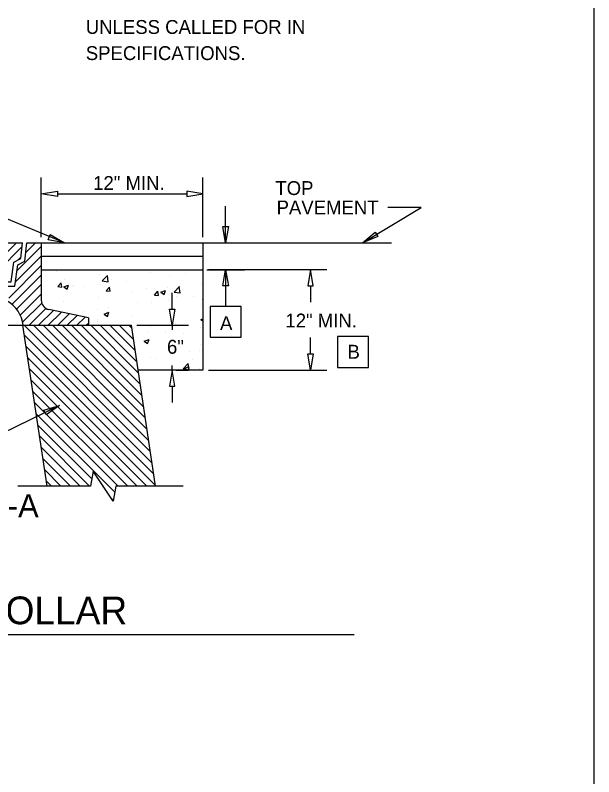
# Model space of a CAD drawing. Extents: x 6712067 to 6713867, y 1867712 to 1869162.
# Drawn here: x 6713616.6 to 6713866.9, y 1868438 to 1868767.4 of the extents above; entities that cross this region are included whole.
import ezdxf

# ---------------------------------------------------------------- set-up
doc = ezdxf.new("R2010")
doc.units = 0
for name, color, linetype in [('Default', 7, 'Continuous'), ('G-MARK', 7, 'Continuous'), ('G-TEXT', 7, 'Continuous'), ('Misc CnstDet(22)', 7, 'Continuous')]:
    doc.layers.add(name, color=color, linetype=linetype)

msp = doc.modelspace()

# ---------------------------------------------------------------- linework, layer by layer
at = {"layer": 'Default'}
msp.add_lwpolyline([(6712066.89, 1869162.31), (6713866.89, 1869162.31), (6713866.89, 1867712.31), (6712066.89, 1867712.31)], close=True, dxfattribs=at)
at = {"layer": 'G-MARK'}
for p, q in [((6713627.89, 1868671.47), (6713627.89, 1868697.18)), ((6713697.84, 1868671.47), (6713697.84, 1868697.18)), ((6713634.89, 1868690.18), (6713690.84, 1868690.18)), ((6713707.65, 1868669.03), (6713707.65, 1868684.86)), ((6713700.3, 1868657.38), (6713751.36, 1868657.38)), ((6713707.65, 1868657.37), (6713707.65, 1868641.51)), ((6713744.36, 1868650.38), (6713744.36, 1868643.33)), ((6713684.53, 1868640.33), (6713684.53, 1868647.33)), ((6713669.31, 1868633.33), (6713691.53, 1868633.33)), ((6713744.36, 1868620.96), (6713744.36, 1868628)), ((6713700.3, 1868613.96), (6713751.36, 1868613.96)), ((6713684.53, 1868606.96), (6713684.53, 1868599.96)), ((6713649.15, 1868563.73), (6713617.8, 1868563.73)), ((6713689.34, 1868563.73), (6713660.17, 1868563.73))]:
    msp.add_line(p, q, dxfattribs=at)
for points in [[(6713637.9, 1868669.03), (6713599.99, 1868684.64), (6713578.45, 1868684.64)], [(6713766.89, 1868669.03), (6713792.25, 1868684.2), (6713777.87, 1868684.2)], [(6713635.84, 1868598.59), (6713604.3, 1868583.37), (6713595.06, 1868583.37)], [(6713660.17, 1868563.73), (6713658.95, 1868557.19), (6713650.39, 1868570.27), (6713649.15, 1868563.73)]]:
    msp.add_lwpolyline(points, dxfattribs=at)
for points in [[(6713700.97, 1868628.11), (6713714.35, 1868628.11), (6713714.35, 1868641.51), (6713700.97, 1868641.51)], [(6713756.08, 1868615.07), (6713769.48, 1868615.07), (6713769.48, 1868628.47), (6713756.08, 1868628.47)]]:
    msp.add_lwpolyline(points, close=True, dxfattribs=at)
at = {"layer": 'G-TEXT'}
for points in [[(6713634.89, 1868691.35), (6713634.89, 1868689.01), (6713627.89, 1868690.18)], [(6713690.84, 1868691.35), (6713690.84, 1868689.01), (6713697.84, 1868690.18)], [(6713708.82, 1868676.03), (6713707.65, 1868669.03), (6713706.5, 1868676.03)], [(6713631.73, 1868672.52), (6713637.9, 1868669.03), (6713630.95, 1868670.34)], [(6713773.47, 1868671.65), (6713766.89, 1868669.03), (6713772.28, 1868673.64)], [(6713706.5, 1868650.37), (6713707.65, 1868657.37), (6713708.82, 1868650.37)], [(6713743.19, 1868650.38), (6713745.53, 1868650.38), (6713744.36, 1868657.38)], [(6713683.36, 1868640.33), (6713685.7, 1868640.33), (6713684.53, 1868633.33)], [(6713743.19, 1868620.96), (6713745.53, 1868620.96), (6713744.36, 1868613.96)], [(6713683.36, 1868606.96), (6713685.7, 1868606.96), (6713684.53, 1868613.96)], [(6713629.02, 1868596.59), (6713635.84, 1868598.59), (6713630.03, 1868594.51)]]:
    msp.add_lwpolyline(points, close=True, dxfattribs=at)
at = {"layer": 'Misc CnstDet(22)'}
for p, q in [((6713697.84, 1868690.18), (6713697.84, 1868690.18)), ((6713472.73, 1868669.03), (6713619.8, 1868669.03)), ((6713605.47, 1868657.37), (6713617.13, 1868669.03)), ((6713609.21, 1868656.96), (6713619.63, 1868667.38)), ((6713617.43, 1868656.96), (6713627.87, 1868667.4)), ((6713621.17, 1868664.83), (6713625.37, 1868669.03)), ((6713621.63, 1868669.03), (6713779.44, 1868669.03)), ((6713627.87, 1868669.03), (6713627.87, 1868644.19)), ((6713627.89, 1868669.04), (6713627.89, 1868669.04)), ((6713697.83, 1868669.03), (6713697.83, 1868613.95)), ((6713697.84, 1868669.04), (6713697.84, 1868669.04)), ((6713616.77, 1868652.16), (6713627.87, 1868663.27)), ((6713618.07, 1868661.71), (6713619.13, 1868662.76)), ((6713627.87, 1868663.2), (6713697.83, 1868663.2)), ((6713613.85, 1868645.11), (6713627.87, 1868659.16)), ((6713627.87, 1868657.37), (6713697.83, 1868657.37)), ((6713634.3, 1868656.68), (6713634.3, 1868656.68)), ((6713667.62, 1868657), (6713667.62, 1868657)), ((6713675.27, 1868656.13), (6713675.27, 1868656.13)), ((6713697.84, 1868657.38), (6713697.84, 1868657.38)), ((6713699.48, 1868657.37), (6713715.84, 1868657.37)), ((6713615.2, 1868642.34), (6713627.87, 1868655.03)), ((6713637.93, 1868653.1), (6713637.93, 1868653.1)), ((6713652.89, 1868655.14), (6713652.89, 1868655.14)), ((6713654.24, 1868652.5), (6713656.52, 1868654.87)), ((6713656.84, 1868652.11), (6713656.52, 1868654.87)), ((6713658.28, 1868653.21), (6713658.28, 1868653.21)), ((6713683.16, 1868654.87), (6713683.16, 1868654.87)), ((6713690.46, 1868655.81), (6713690.46, 1868655.81)), ((6713617.22, 1868640.25), (6713627.87, 1868650.9)), ((6713635.08, 1868650.02), (6713636.48, 1868651.7)), ((6713635.08, 1868650.02), (6713636.8, 1868649.86)), ((6713636.8, 1868649.86), (6713636.48, 1868651.7)), ((6713637.67, 1868649.89), (6713639.72, 1868650.67)), ((6713637.67, 1868649.89), (6713639.12, 1868648.92)), ((6713639.12, 1868648.9), (6713639.72, 1868650.67)), ((6713641.28, 1868650.28), (6713641.28, 1868650.28)), ((6713642.36, 1868650.64), (6713642.36, 1868650.64)), ((6713646.42, 1868650.02), (6713646.42, 1868650.02)), ((6713653.72, 1868650.99), (6713653.72, 1868650.99)), ((6713654.24, 1868652.5), (6713656.84, 1868652.11)), ((6713655.97, 1868648.19), (6713657.39, 1868649.86)), ((6713657.71, 1868648.03), (6713657.39, 1868649.86)), ((6713657.92, 1868650), (6713657.92, 1868650)), ((6713664.76, 1868652.43), (6713664.76, 1868652.43)), ((6713673.48, 1868649.34), (6713673.48, 1868649.34)), ((6713682.41, 1868649.5), (6713682.41, 1868649.5)), ((6713685.37, 1868647.68), (6713687.64, 1868650.05)), ((6713687.94, 1868647.27), (6713687.62, 1868650.05)), ((6713697.37, 1868651.54), (6713697.37, 1868651.54)), ((6713618.79, 1868637.7), (6713627.87, 1868646.79)), ((6713628.01, 1868647.59), (6713628.01, 1868647.59)), ((6713655.97, 1868648.19), (6713657.71, 1868648.03)), ((6713667.26, 1868647.32), (6713667.26, 1868647.32)), ((6713676.87, 1868646.35), (6713678.3, 1868648.03)), ((6713676.87, 1868646.35), (6713678.62, 1868646.21)), ((6713678.62, 1868646.21), (6713678.3, 1868648.03)), ((6713679.56, 1868647.57), (6713681.6, 1868648.35)), ((6713679.56, 1868647.57), (6713681.01, 1868646.58)), ((6713681.01, 1868646.58), (6713681.6, 1868648.33)), ((6713685.37, 1868647.68), (6713687.96, 1868647.29)), ((6713689.04, 1868648.67), (6713689.04, 1868648.67)), ((6713619.82, 1868634.6), (6713628.1, 1868642.89)), ((6713637.58, 1868643.39), (6713637.58, 1868643.39)), ((6713652.55, 1868645.43), (6713652.55, 1868645.43)), ((6713669.42, 1868643), (6713669.42, 1868643)), ((6713675.5, 1868643.37), (6713675.5, 1868643.37)), ((6713682.8, 1868644.33), (6713682.8, 1868644.33)), ((6713686.4, 1868645.92), (6713686.4, 1868645.92)), ((6713693.83, 1868645.78), (6713693.83, 1868645.78)), ((6713697.78, 1868644.54), (6713697.83, 1868644.59)), ((6713697.78, 1868644.54), (6713697.83, 1868644.54)), ((6713622.66, 1868633.32), (6713629.94, 1868640.61)), ((6713626.77, 1868633.32), (6713633.18, 1868639.72)), ((6713648.28, 1868636.58), (6713631.18, 1868640.13)), ((6713646.05, 1868639.49), (6713646.05, 1868639.49)), ((6713652.41, 1868640.09), (6713652.41, 1868640.09)), ((6713657.09, 1868640.94), (6713657.09, 1868640.94)), ((6713682.04, 1868639.79), (6713682.04, 1868639.79)), ((6713697, 1868641.83), (6713697, 1868641.83)), ((6713630.9, 1868633.32), (6713636.6, 1868639.01)), ((6713635.01, 1868633.32), (6713640.01, 1868638.3)), ((6713639.14, 1868633.32), (6713643.41, 1868637.59)), ((6713643.27, 1868633.32), (6713646.83, 1868636.87)), ((6713648.28, 1868636.58), (6713648.28, 1868633.32)), ((6713655.07, 1868638.16), (6713657.11, 1868638.94)), ((6713655.07, 1868638.16), (6713656.52, 1868637.17)), ((6713656.52, 1868637.17), (6713657.11, 1868638.94)), ((6713666.91, 1868637.61), (6713666.91, 1868637.61)), ((6713696.96, 1868635.82), (6713697.83, 1868636.16)), ((6713425.68, 1868633.32), (6713666.87, 1868633.32)), ((6713630.44, 1868563.73), (6713620, 1868633.32)), ((6713675.06, 1868578.69), (6713620.44, 1868633.32)), ((6713674.33, 1868583.54), (6713624.57, 1868633.32)), ((6713673.62, 1868588.4), (6713628.68, 1868633.32)), ((6713672.88, 1868593.24), (6713632.81, 1868633.32)), ((6713672.15, 1868598.09), (6713636.94, 1868633.32)), ((6713671.41, 1868602.95), (6713641.05, 1868633.32)), ((6713670.7, 1868607.79), (6713645.18, 1868633.32)), ((6713647.38, 1868633.32), (6713648.28, 1868634.21)), ((6713669.97, 1868612.66), (6713649.29, 1868633.32)), ((6713652.18, 1868635.73), (6713652.18, 1868635.73)), ((6713652.25, 1868635.11), (6713652.25, 1868635.11)), ((6713669.23, 1868617.5), (6713653.42, 1868633.32)), ((6713668.5, 1868622.35), (6713657.55, 1868633.32)), ((6713667.79, 1868627.21), (6713661.66, 1868633.32)), ((6713667.05, 1868632.05), (6713665.79, 1868633.32)), ((6713677.31, 1868563.73), (6713666.87, 1868633.32)), ((6713666.88, 1868633.33), (6713666.88, 1868633.33)), ((6713667.81, 1868634.44), (6713667.81, 1868634.44)), ((6713683.35, 1868633.78), (6713683.35, 1868633.78)), ((6713684.53, 1868633.33), (6713684.53, 1868631.31)), ((6713684.53, 1868633.33), (6713684.53, 1868633.33)), ((6713686.17, 1868634.28), (6713686.17, 1868634.28)), ((6713696.96, 1868635.82), (6713697.83, 1868635.22)), ((6713667.83, 1868631.87), (6713667.83, 1868631.87)), ((6713673.94, 1868630.52), (6713673.94, 1868630.52)), ((6713675.13, 1868632.83), (6713675.13, 1868632.83)), ((6713681.69, 1868630.08), (6713681.69, 1868630.08)), ((6713689.5, 1868629.87), (6713689.5, 1868629.87)), ((6713696.66, 1868632.15), (6713696.66, 1868632.15)), ((6713675.8, 1868573.85), (6713620.64, 1868628.98)), ((6713672.47, 1868626.43), (6713674.51, 1868627.21)), ((6713672.47, 1868626.43), (6713673.91, 1868625.44)), ((6713673.91, 1868625.44), (6713674.51, 1868627.21)), ((6713676.53, 1868568.98), (6713621.38, 1868624.14)), ((6713668.2, 1868625.6), (6713668.2, 1868625.6)), ((6713696.91, 1868625.21), (6713696.91, 1868625.21)), ((6713692.18, 1868622.14), (6713692.18, 1868622.14)), ((6713696.31, 1868622.44), (6713696.31, 1868622.44)), ((6713677.24, 1868564.14), (6713622.11, 1868619.29)), ((6713675.2, 1868619.2), (6713675.2, 1868619.2)), ((6713677.56, 1868618.97), (6713677.56, 1868618.97)), ((6713689.22, 1868614.47), (6713691.49, 1868616.84)), ((6713691.82, 1868614.06), (6713691.49, 1868616.84)), ((6713693.12, 1868618.31), (6713693.12, 1868618.31)), ((6713673.52, 1868563.73), (6713622.85, 1868614.43)), ((6713697.83, 1868613.95), (6713669.76, 1868613.95)), ((6713683.82, 1868613.96), (6713683.82, 1868613.96)), ((6713684.53, 1868613.96), (6713684.53, 1868615.98)), ((6713686.27, 1868613.96), (6713691.53, 1868613.96)), ((6713689.22, 1868614.47), (6713691.82, 1868614.06)), ((6713689.86, 1868614.68), (6713691.91, 1868615.46)), ((6713689.86, 1868614.68), (6713690.97, 1868613.95)), ((6713691.4, 1868613.95), (6713691.91, 1868615.46)), ((6713696.54, 1868614.68), (6713696.54, 1868614.68)), ((6713697.84, 1868613.96), (6713697.84, 1868613.96)), ((6713744.36, 1868613.96), (6713744.36, 1868613.96)), ((6713669.42, 1868563.73), (6713623.56, 1868609.58)), ((6713665.28, 1868563.73), (6713624.29, 1868604.72)), ((6713661.18, 1868563.73), (6713625.03, 1868599.88)), ((6713659.68, 1868561.11), (6713625.76, 1868595.03)), ((6713649.75, 1868566.92), (6713626.47, 1868590.17)), ((6713648.81, 1868563.73), (6713627.21, 1868585.33)), ((6713644.67, 1868563.73), (6713627.94, 1868580.48)), ((6713640.57, 1868563.73), (6713628.68, 1868575.62)), ((6713636.43, 1868563.73), (6713629.39, 1868570.77)), ((6713632.3, 1868563.73), (6713630.12, 1868565.93)), ((6713659.02, 1868557.62), (6713657.96, 1868558.7)), ((6713347.68, 1868499.57), (6713763.18, 1868499.57))]:
    msp.add_line(p, q, dxfattribs=at)
for points in [[(6713470.91, 1868669.03), (6713471.74, 1868661.11), (6713474.74, 1868659.48), (6713476.03, 1868650.28), (6713616.51, 1868650.28), (6713617.78, 1868659.48), (6713620.78, 1868661.11), (6713621.63, 1868669.03)], [(6713472.73, 1868669.03), (6713473.46, 1868662.26), (6713476.44, 1868660.65), (6713477.61, 1868652.09), (6713614.93, 1868652.09), (6713616.1, 1868660.65), (6713619.08, 1868662.26), (6713619.8, 1868669.03)]]:
    msp.add_lwpolyline(points, dxfattribs=at)
for centre, radius, start, end in [((6713606.58, 1868631.96), 13.49, 5.7578, 60.7854), ((6713632.02, 1868644.19), 4.14, 180, 258.2246)]:
    msp.add_arc(centre, radius, start, end, dxfattribs=at)

# ---------------------------------------------------------------- texts
for s, height, p in [('UNLESS CALLED FOR IN', 6, (6713647.16, 1868759.35)), ('SPECIFICATIONS.', 6, (6713647.16, 1868748.04)), ('12" MIN.', 6, (6713650.34, 1868691.85)), ('TOP', 6, (6713729.15, 1868689.66)), ('PAVEMENT', 6, (6713729.69, 1868681.29)), ('A', 6, (6713705.22, 1868631.25)), ('B', 6, (6713760.37, 1868618.86)), ('SECTION A-A', 10, (6713541.35, 1868550.24)), ('AND REINFORCED CONCRETE COLLAR', 12, (6713357.48, 1868504))]:
    msp.add_text(s, height=height, dxfattribs=at).set_placement(p)
for s, p in [('12" MIN.', (6713733.51, 1868632.36)), ('6"', (6713682.29, 1868621.01))]:
    msp.add_text(s, height=6, rotation=0.001, dxfattribs=at).set_placement(p)

doc.saveas('drawing.dxf')
